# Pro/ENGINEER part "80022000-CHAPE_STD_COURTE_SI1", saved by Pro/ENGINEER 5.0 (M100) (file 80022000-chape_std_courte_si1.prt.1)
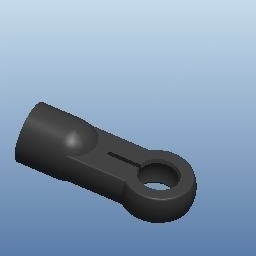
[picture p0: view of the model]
Units: millimeter Newton Second (mmNs); MM, TONNE, HOURS
Materials in the file: NYLON

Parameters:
  PTC_MATERIAL_NAME = "NYLON"

Other named items: O_CHAPE, DROITE, DESSUS, FACE, 80022000-CHAPE_STD_COURTE_01_1

Layers: 01_AXES, 02_POINTS, 03_PLANS, 05_SURFACES, 06_REPERES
